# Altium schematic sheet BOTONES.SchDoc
size A
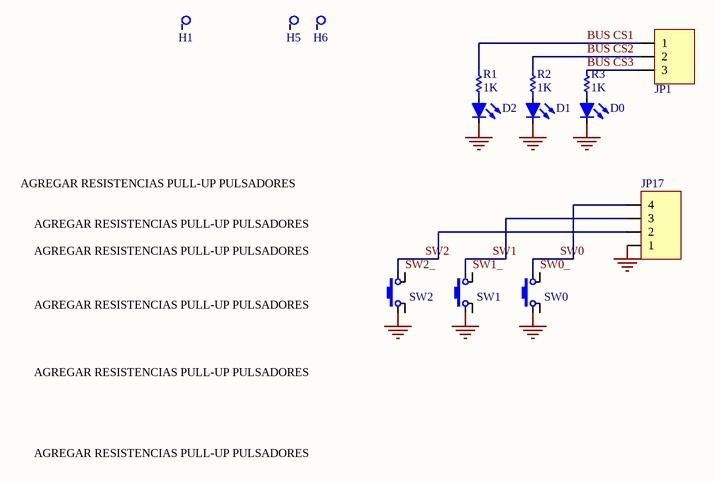
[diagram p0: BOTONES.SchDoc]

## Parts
D0  Led 5mm Rojo Difuso  [LED5mm ROJO]  (value not drawn)
D1  Led 5mm Rojo Difuso  [LED5mm ROJO]  (value not drawn)
D2  Led 5mm Rojo Difuso  [LED5mm ROJO]  (value not drawn)
H1  Agujero de Montaje  [agujero]  (value not drawn)  (no BOM)
H5  Agujero de Montaje  [agujero]  (value not drawn)  (no BOM)
H6  Agujero de Montaje  [agujero]  (value not drawn)  (no BOM)
JP1  Header3x1  [CONPOL3X1_90]  (value not drawn)
JP17  Header4x1  [CONPOL4x1_90]  (value not drawn)
R1  value 1K  [1206NP]  (hidden comment: Res)
R2  value 1K  [1206NP]  (hidden comment: Res)
R3  value 1K  [1206NP]  (hidden comment: Res)
SW0  SW_T_5MM  [SW_T_5MM]  (value not drawn)
SW1  SW_T_5MM  [SW_T_5MM]  (value not drawn)
SW2  SW_T_5MM  [SW_T_5MM]  (value not drawn)

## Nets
GND: D0.2(K) D1.2(K) D2.2(K) JP17.1 SW0.3 SW1.3 SW2.3
BUS CS1: JP1.1 R1.2
BUS CS2: JP1.2 R2.2
BUS CS3: JP1.3 R3.2
SW0: JP17.4 SW0.4
SW0_: SW0.2
SW1: JP17.3 SW1.4
SW1_: SW1.2
SW2: JP17.2 SW2.4
SW2_: SW2.2
NetD0_1: D0.1(A) R3.1
NetD1_1: D1.1(A) R2.1
NetD2_1: D2.1(A) R1.1

Not connected (* = marked no-connect by the designer): H1 1; H5 1; H6 1; SW0 1; SW1 1; SW2 1

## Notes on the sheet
- AGREGAR RESISTENCIAS PULL-UP PULSADORES

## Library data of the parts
D0-D2 = Led 5mm Rojo Difuso: Codigo Ebay: NA; Dolares Ebay: 0.06
JP1 = Header3x1: Header 3x1
JP17 = Header4x1: Header 4x1
R1-R3 = Res: Resistor; Power: 0.25W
